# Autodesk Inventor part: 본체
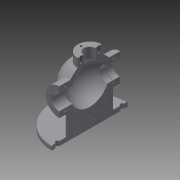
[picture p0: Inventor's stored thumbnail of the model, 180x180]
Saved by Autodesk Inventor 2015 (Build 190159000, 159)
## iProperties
Created: 2020-08
Part Number: 본체
Material: 일반
Document SubType Name: Modeling
Designer: 101548
Density: 1 g/cm^3
Appearance: 기본값
Author: 101548
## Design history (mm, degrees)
sketch "스케치1"
  geometry: L1 (53, 0)-(-53, 0); A1 r 53 centre (0, 0) between (53, 0) and (-53, 0); 2 further points
  constraints: 2 end point, 2 point on circle, 1 centre point, 1 coincident, 1 horizontal, 1 midpoint
  dimensions: "d0" = 106 distance of L1.start L1.end; "d1" = 53 radius of A1
revolve "회전1" sketch "스케치1" stored, may be unused: angle "d2" = 90 deg
sketch "스케치2"
  geometry: L1 (43, 0)-(-43, 0); A1 r 43 centre (0, 0) between (43, 0) and (-43, 0); 2 further points
  constraints: 2 end point, 2 point on circle, 1 centre point, 1 coincident, 1 horizontal, 1 midpoint
  dimensions: "d3" = 86 distance of L1.start L1.end; "d4" = 43 radius of A1
revolve "회전2" sketch "스케치2" stored, may be unused: angle "d5" = 90 deg
node "작업 평면1"
sketch "스케치3"
  geometry: C1 r 85 at (0, 0); 1 further point
  constraints: 1 centre point, 1 coincident
  dimensions: "d7" = 170 diameter of C1
extrude "돌출1" join sketch "스케치3" distance "d8" = 10; taper "d9" = 0 deg
sketch "스케치4"
  geometry: C1 r 85 at (0, 0) reference; 1 further point
  constraints: 1 vertical alignment
  dimensions: "d10" = 72.5 distance of C1.centre point (0, -72.5)
hole "구멍1" sketch "스케치4" at (0, -72.5) diameter "d11" = 9; stored, may be unused: countersink angle "d15" = 90 deg, drill point angle "d17" = 118 deg; dims "d12" = 6, "d13" = 4, "d14" = 2, "d16" = 8
sketch "스케치5"
  geometry: L1 (4, -52)-(-4, -52); L2 (-4, -52)-(-4, 52); L3 (-4, 52)-(4, 52); L4 (4, 52)-(4, -52); L5 (4, -52)-(-4, 52); L6 (-4, -52)-(4, 52); L7 (-43, -4)-(43, -4); L8 (43, -4)-(43, 4); L9 (43, 4)-(-43, 4); L10 (-43, 4)-(-43, -4); L11 (-43, -4)-(43, 4); L12 (43, -4)-(-43, 4); C1 r 85 at (0, 0) reference
  constraints: 24 end point, 4 midpoint, 4 parallel, 2 horizontal, 2 perpendicular
  dimensions: "d21" = 8 distance of L2.end L3.end; "d22" = 8 distance of L9.end L7.start; "d23" = 86 distance of L8.end L9.end; "d24" = 104 distance of L3.end L1.start
extrude "돌출2" join sketch "스케치5" stored distance "d25" = 75; taper "d26" = 0 deg
node "작업 평면2"
sketch "스케치6"
  geometry: C1 r 31 at (0, 0); 1 further point
  constraints: 1 centre point, 1 coincident
  dimensions: "d28" = 62 diameter of C1
extrude "돌출3" join sketch "스케치6" stored distance "d29" = 75; taper "d30" = 0 deg
sketch "스케치7"
  geometry: C1 r 31 at (0, 0) reference; C2 r 17.5 at (0, 0)
  constraints: 1 centre point, 1 coincident
  dimensions: "d31" = 35 diameter of C2
extrude "돌출4" cut sketch "스케치7" stored distance "d32" = 16; taper "d33" = 0 deg
node "작업 평면4"
sketch "스케치9"
  geometry: C1 r 27 at (0, 0); 1 further point
  constraints: 1 centre point, 1 coincident
  dimensions: "d39" = 54 diameter of C1
extrude "돌출6" join sketch "스케치9" stored distance "d40" = 1.75; taper "d41" = 0 deg
sketch "스케치10"
  geometry: C1 r 27 at (0, 0) reference; C2 r 13 at (0, 0)
  constraints: 1 centre point, 1 coincident
  dimensions: "d42" = 26 diameter of C2
extrude "돌출7" cut sketch "스케치10" stored distance "d43" = 1.75; taper "d44" = 0 deg
sketch "스케치11"
  geometry: C1 r 17.5 at (0, 0) reference; 1 further point
  constraints: 1 vertical alignment
  dimensions: "d45" = 24 distance of C1.centre point (0, 24)
hole "구멍2" sketch "스케치11" at (0, 24) diameter "d46" = 3.242; stored, may be unused: countersink angle "d50" = 90 deg, drill point angle "d52" = 118 deg; dims "d47" = 12, "d48" = 4, "d49" = 2, "d51" = 15
sketch "스케치12"
  geometry: C1 r 17.5 at (0, 0) reference; 1 further point
  constraints: 1 vertical alignment
  dimensions: "d56" = 24 distance of C1.centre point (0, -24)
hole "구멍3" sketch "스케치12" at (0, -24) diameter "d57" = 3.242; stored, may be unused: countersink angle "d61" = 90 deg, drill point angle "d63" = 118 deg; dims "d58" = 12, "d59" = 4, "d60" = 2, "d62" = 15
sketch "스케치13"
  geometry: C1 r 13 at (0, 0) reference; 1 further point
  constraints: 1 vertical alignment
  dimensions: "d67" = 20 distance of C1.centre point (0, 20)
hole "구멍4" sketch "스케치13" at (0, 20) diameter "d68" = 4.134; stored, may be unused: countersink angle "d72" = 90 deg, drill point angle "d74" = 118 deg; dims "d69" = 10, "d70" = 4, "d71" = 2, "d73" = 14.2
chamfer "모따기1" distance "d78" = 1; stored, may be unused: second distance "d79" = 2, angle "d80" = 45 deg
fillet "모깎기1" dims "d81" = 3
fillet "모깎기2" dims "d82" = 3
fillet "모깎기3" dims "d83" = 3
fillet "모깎기4" dims "d84" = 3
fillet "모깎기5" dims "d85" = 3
node "작업 평면5"
sketch "스케치14"
  geometry: L1 (27, 0)-(-27, 0) reference; 2 further points
  constraints: 1 other
  dimensions: "d86" = 9 distance from line of L1 point (0, -9); "d87" = 27 horizontal distance of L1.end point (0, -9)
feature "엠보싱1" sketch "스케치14" dims "d10" = 72.5, "d88" = 0.5, "d89" = 0
node "작업 평면6"
sketch "스케치15"
  geometry: C1 r 18.5 at (0, 0); 1 further point
  constraints: 1 centre point, 1 coincident
  dimensions: "d91" = 37 diameter of C1
extrude "돌출8" cut sketch "스케치15" distance "d92" = 1.75; taper "d93" = 0 deg
node "솔리드1"
pattern_circular "원형 패턴1" dims angle "d19" = 360 deg
mirror "대칭1"
pattern_circular "원형 패턴2" dims angle "d54" = 360 deg
pattern_circular "원형 패턴3" dims angle "d65" = 360 deg
pattern_circular "원형 패턴4" dims angle "d76" = 360 deg
other parameters: "d6" = -85, "d27" = -68, "d90" = -16
